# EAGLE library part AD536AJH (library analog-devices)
ANALOG DEVICES
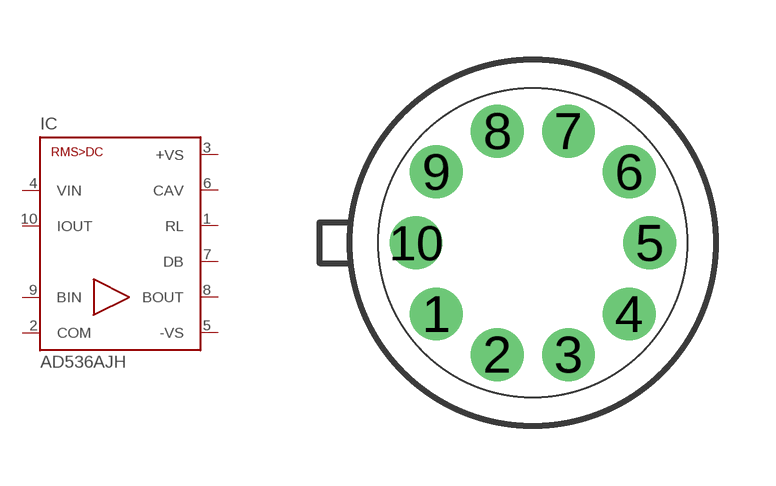
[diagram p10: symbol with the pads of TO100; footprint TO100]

Designator prefix IC

## AD536AJH (MF: ALTERA CORPORATION; MPN: AD536AJH; OC_FARNELL: 405360; OC_NEWARK: 05F6940)  [TO100]
1  RL  pas
2  COM  pwr
3  +VS  pwr
4  VIN  in
5  -VS  pwr
6  CAV  out
7  DB  out
8  BOUT  out
9  BIN  in
10  IOUT  out

## Footprint TO100 (pad centres in mm)
Metal Can Package
drill 0.813 round: 1 -2.413,-1.778; 2 -0.889,-2.794; 3 0.889,-2.794; 4 2.413,-1.778; 5 2.921,0; 6 2.413,1.778; 7 0.889,2.794; 8 -0.889,2.794; 9 -2.413,1.778; 10 -2.921,0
